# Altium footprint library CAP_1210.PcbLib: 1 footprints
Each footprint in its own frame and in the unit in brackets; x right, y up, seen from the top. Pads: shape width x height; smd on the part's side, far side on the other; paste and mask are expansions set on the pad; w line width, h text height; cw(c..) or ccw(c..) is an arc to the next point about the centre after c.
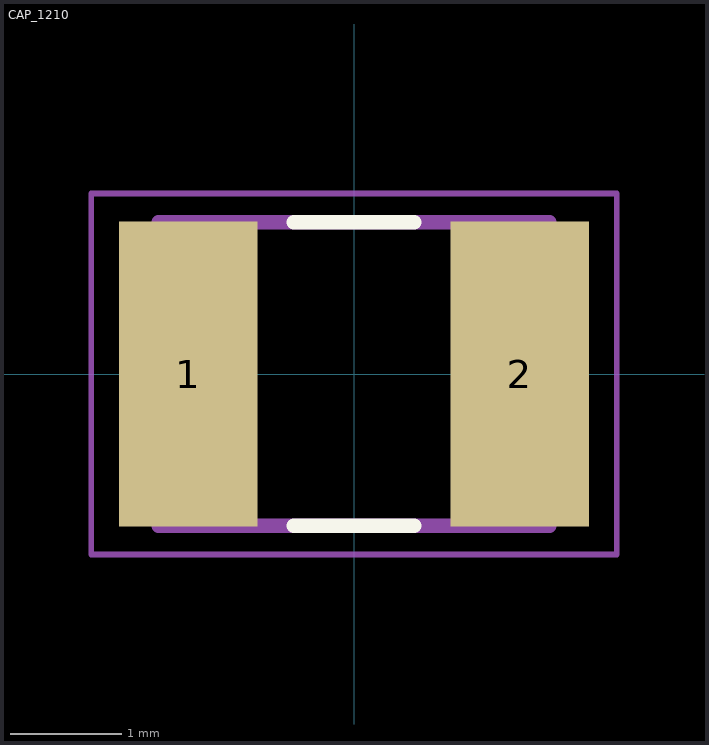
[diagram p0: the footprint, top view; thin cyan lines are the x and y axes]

## CAP_1210 [mm]
pads (2):
  rect 1.24x2.73 smd: 1(-1.485,0) 2(1.485,0)
Top Overlay:
  lines w0.127: -0.54,-1.36 0.54,-1.36 ; -0.54,1.36 0.54,1.36
Mechanical 13:
  lines w0.127: -1.75,-1.36 -1.75,1.36 1.75,1.36 1.75,-1.36 -1.75,-1.36
Mechanical 15:
  lines w0.05: -2.355,-1.617 -2.355,1.617 2.355,1.617 2.355,-1.617 -2.355,-1.617
3D body "CAP_1210.STEP": height 1.97, standoff -0.03, extent -1.6,-1.25 1.6,1.25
